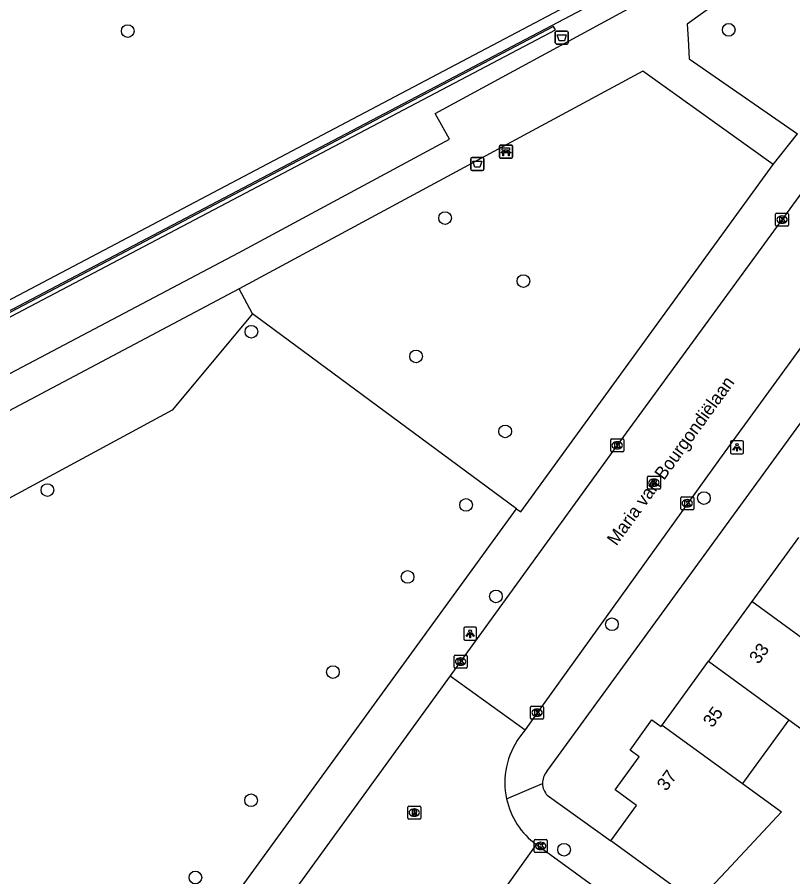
# Model space of a CAD drawing. Extents: x 159675 to 160530, y 382179 to 382901.
# Drawn here: x 160100.6 to 160160.3, y 382626.9 to 382693.1 of the extents above; entities that cross this region are included whole.
import ezdxf

# ---------------------------------------------------------------- set-up
doc = ezdxf.new("R2010")
doc.units = 0
for name, color, linetype in [('IMGEO_Afvalbak', 7, 'Continuous'), ('IMGEO_Bank', 7, 'Continuous'), ('IMGEO_Boom', 7, 'Continuous'), ('IMGEO_Groenvoorziening', 7, 'Continuous'), ('IMGEO_Haag', 7, 'Continuous'), ('IMGEO_Hek', 7, 'Continuous'), ('IMGEO_Kolk', 7, 'Continuous'), ('IMGEO_Lichtpunt', 7, 'Continuous'), ('IMGEO_Openbare_ruimte_label', 7, 'Continuous'), ('IMGEO_Pand', 7, 'Continuous'), ('IMGEO_Pand_nummerreeks', 7, 'Continuous'), ('IMGEO_Rijbaan_lokaal_open', 7, 'Continuous'), ('IMGEO_Rioolput', 7, 'Continuous'), ('IMGEO_Voetpad_halfverhard', 7, 'Continuous'), ('IMGEO_Voetpad_open', 7, 'Continuous')]:
    doc.layers.add(name, color=color, linetype=linetype)

msp = doc.modelspace()

# ---------------------------------------------------------------- linework, layer by layer
at = {"layer": 'IMGEO_Afvalbak'}
for p, q in [((160142.023, 382691.123), (160142.023, 382691.923)), ((160142.023, 382691.923), (160142.023, 382691.123)), ((160142.123, 382692.023), (160142.913, 382692.023)), ((160142.913, 382692.023), (160142.123, 382692.023)), ((160143.013, 382691.923), (160143.013, 382691.123)), ((160143.013, 382691.123), (160143.013, 382691.923)), ((160142.913, 382691.023), (160142.123, 382691.023)), ((160142.123, 382691.023), (160142.913, 382691.023)), ((160135.62, 382682.278), (160136.41, 382682.278)), ((160136.41, 382682.278), (160135.62, 382682.278)), ((160135.52, 382681.378), (160135.52, 382682.178)), ((160135.52, 382682.178), (160135.52, 382681.378)), ((160136.51, 382682.178), (160136.51, 382681.378)), ((160136.51, 382681.378), (160136.51, 382682.178)), ((160136.41, 382681.278), (160135.62, 382681.278)), ((160135.62, 382681.278), (160136.41, 382681.278))]:
    msp.add_line(p, q, dxfattribs=at)
for points in [[(160142.166, 382691.737), (160142.87, 382691.737), (160142.721, 382691.267), (160142.315, 382691.267), (160142.166, 382691.737)], [(160135.663, 382681.992), (160136.367, 382681.992), (160136.218, 382681.522), (160135.812, 382681.522), (160135.663, 382681.992)]]:
    msp.add_lwpolyline(points, dxfattribs=at)
for centre, start, end in [((160142.123, 382691.923), 90, 180), ((160142.123, 382691.923), 90, 180), ((160142.913, 382691.923), 0, 90), ((160142.913, 382691.923), 360, 90), ((160142.123, 382691.123), 180, 270), ((160142.123, 382691.123), 180, 270), ((160142.913, 382691.123), 270, 0), ((160142.913, 382691.123), 270, 0), ((160135.62, 382682.178), 90, 180), ((160135.62, 382682.178), 90, 180), ((160136.41, 382682.178), 0, 90), ((160136.41, 382682.178), 360, 90), ((160135.62, 382681.378), 180, 270), ((160135.62, 382681.378), 180, 270), ((160136.41, 382681.378), 270, 0), ((160136.41, 382681.378), 270, 0)]:
    msp.add_arc(centre, 0.1, start, end, dxfattribs=at)
at = {"layer": 'IMGEO_Bank'}
for p, q in [((160137.722, 382682.311), (160137.722, 382683.152)), ((160137.722, 382683.152), (160137.722, 382682.311)), ((160137.797, 382683.236), (160138.638, 382683.236)), ((160138.638, 382683.236), (160137.797, 382683.236)), ((160138.722, 382683.161), (160138.722, 382682.32)), ((160138.722, 382682.32), (160138.722, 382683.161)), ((160138.419, 382682.634), (160138.026, 382682.634)), ((160138.031, 382682.742), (160138.031, 382682.848)), ((160138.075, 382682.848), (160138.075, 382682.742)), ((160138.363, 382682.854), (160138.081, 382682.854)), ((160138.081, 382682.736), (160138.363, 382682.736)), ((160138.369, 382682.742), (160138.369, 382682.848)), ((160138.413, 382682.848), (160138.413, 382682.742)), ((160138.647, 382682.236), (160137.806, 382682.236)), ((160137.806, 382682.236), (160138.647, 382682.236))]:
    msp.add_line(p, q, dxfattribs=at)
for points in [[(160138.025, 382682.854), (160137.939, 382682.854), (160137.939, 382683.015), (160138.502, 382683.015), (160138.502, 382682.854), (160138.419, 382682.854)], [(160137.969, 382682.634), (160137.827, 382682.634), (160137.939, 382682.736), (160138.025, 382682.736)], [(160138.019, 382682.627), (160138.019, 382682.42), (160137.976, 382682.42), (160137.976, 382682.627)], [(160138.419, 382682.736), (160138.502, 382682.736), (160138.614, 382682.634), (160138.475, 382682.634)], [(160138.469, 382682.627), (160138.469, 382682.42), (160138.425, 382682.42), (160138.425, 382682.627)]]:
    msp.add_lwpolyline(points, dxfattribs=at)
for centre, radius, start, end in [((160137.8, 382683.158), 0.0779, 92.4484, 184.28452), ((160137.8, 382683.158), 0.0779, 92.4484, 184.28452), ((160138.644, 382683.158), 0.0779, 2.4484, 94.28452), ((160138.644, 382683.158), 0.0779, 2.4484, 94.28452), ((160137.8, 382682.314), 0.0779, 182.4484, 274.28452), ((160137.8, 382682.314), 0.0779, 182.4484, 274.28452), ((160137.969, 382682.627), 0.00671, 2.89567, 87.10433), ((160138.026, 382682.627), 0.00671, 92.89567, 177.10433), ((160138.024, 382682.847), 0.00671, 2.89567, 87.10433), ((160138.024, 382682.743), 0.00671, 272.89567, 357.10433), ((160138.081, 382682.847), 0.00671, 92.89567, 177.10433), ((160138.081, 382682.743), 0.00671, 182.89567, 267.10433), ((160138.363, 382682.847), 0.00671, 2.89567, 87.10433), ((160138.363, 382682.743), 0.00671, 272.89567, 357.10433), ((160138.42, 382682.847), 0.00671, 92.89567, 177.10433), ((160138.42, 382682.743), 0.00671, 182.89567, 267.10433), ((160138.418, 382682.627), 0.00671, 2.89567, 87.10433), ((160138.475, 382682.627), 0.00671, 92.89567, 177.10433), ((160138.644, 382682.314), 0.0779, 272.4484, 4.28452), ((160138.644, 382682.314), 0.0779, 272.4484, 4.28452)]:
    msp.add_arc(centre, radius, start, end, dxfattribs=at)
at = {"layer": 'IMGEO_Boom'}
for centre in [(160109.074, 382692.021), (160155.384, 382692.115), (160133.528, 382677.612), (160139.568, 382672.758), (160118.608, 382668.855), (160131.298, 382666.954), (160138.16, 382661.171), (160102.892, 382656.654), (160153.471, 382656.038), (160135.153, 382655.509), (160130.636, 382649.963), (160137.452, 382648.464), (160146.382, 382646.319), (160124.888, 382642.636), (160118.576, 382632.758), (160142.699, 382628.945), (160114.289, 382626.806)]:
    msp.add_circle(centre, 0.489, dxfattribs=at)
at = {"layer": 'IMGEO_Groenvoorziening'}
for points in [[(160028.302, 382652.839), (160035.617, 382637.39), (160147.024, 382696.155), (160135.659, 382717.176)], [(160118.682, 382670.24), (160117.651, 382672.153)], [(160118.682, 382670.24), (160112.498, 382662.82), (160085.741, 382648.366), (160074.078, 382641.993)], [(160139.025, 382655.211), (160118.682, 382670.24)]]:
    msp.add_lwpolyline(points, dxfattribs=at)
at = {"layer": 'IMGEO_Haag'}
msp.add_lwpolyline([(160142.038, 382692.112), (160141.896, 382692.376), (160088.197, 382664.142), (160088.386, 382663.89), (160142.038, 382692.112)], dxfattribs=at)
at = {"layer": 'IMGEO_Hek'}
msp.add_lwpolyline([(160023.484, 382662.997), (160024.119, 382661.659), (160025.128, 382659.531), (160027.238, 382655.082), (160028.302, 382652.839), (160035.908, 382636.803), (160148.158, 382695.844), (160136.928, 382717.961), (160135.789, 382720.203), (160134.215, 382723.303), (160133.5, 382724.713), (160132.248, 382727.178), (160131.343, 382728.961)], dxfattribs=at)
at = {"layer": 'IMGEO_Kolk'}
for p, q in [((160159, 382677.068), (160159, 382677.92)), ((160159.075, 382677.994), (160159.927, 382677.994)), ((160159.488, 382677.774), (160159.513, 382677.774)), ((160160.001, 382677.92), (160160.001, 382677.068)), ((160159.927, 382676.994), (160159.075, 382676.994)), ((160159.511, 382677.214), (160159.486, 382677.214)), ((160146.291, 382659.678), (160146.291, 382660.53)), ((160146.366, 382660.604), (160147.218, 382660.604)), ((160146.779, 382660.384), (160146.804, 382660.384)), ((160147.292, 382660.53), (160147.292, 382659.678)), ((160146.802, 382659.824), (160146.777, 382659.824)), ((160147.218, 382659.604), (160146.366, 382659.604)), ((160151.686, 382655.213), (160151.686, 382656.065)), ((160151.761, 382656.139), (160152.613, 382656.139)), ((160152.174, 382655.919), (160152.199, 382655.919)), ((160152.687, 382656.065), (160152.687, 382655.213)), ((160152.613, 382655.139), (160151.761, 382655.139)), ((160152.197, 382655.359), (160152.172, 382655.359)), ((160134.222, 382643.019), (160134.222, 382643.871)), ((160134.297, 382643.945), (160135.149, 382643.945)), ((160135.223, 382643.871), (160135.223, 382643.019)), ((160134.733, 382643.165), (160134.708, 382643.165)), ((160134.71, 382643.725), (160134.735, 382643.725)), ((160135.149, 382642.945), (160134.297, 382642.945)), ((160140.119, 382639.079), (160140.119, 382639.931)), ((160140.194, 382640.005), (160141.046, 382640.005)), ((160141.12, 382639.931), (160141.12, 382639.079)), ((160140.63, 382639.225), (160140.605, 382639.225)), ((160140.607, 382639.785), (160140.632, 382639.785)), ((160141.046, 382639.005), (160140.194, 382639.005)), ((160140.4, 382628.811), (160140.4, 382629.663)), ((160140.475, 382629.737), (160141.327, 382629.737)), ((160140.888, 382629.517), (160140.913, 382629.517)), ((160141.401, 382629.663), (160141.401, 382628.811)), ((160141.327, 382628.737), (160140.475, 382628.737)), ((160140.911, 382628.957), (160140.886, 382628.957))]:
    msp.add_line(p, q, dxfattribs=at)
for points in [[(160159, 382677.068), (160159, 382677.92)], [(160159.075, 382677.994), (160159.927, 382677.994)], [(160159.321, 382677.694), (160159.444, 382677.694), (160159.444, 382677.543), (160159.574, 382677.694), (160159.738, 382677.694), (160159.592, 382677.543), (160159.745, 382677.294), (160159.593, 382677.294), (160159.508, 382677.458), (160159.444, 382677.391), (160159.444, 382677.294), (160159.321, 382677.294), (160159.321, 382677.694)], [(160160.001, 382677.92), (160160.001, 382677.068)], [(160159.927, 382676.994), (160159.075, 382676.994)], [(160146.291, 382659.678), (160146.291, 382660.53)], [(160146.366, 382660.604), (160147.218, 382660.604)], [(160147.292, 382660.53), (160147.292, 382659.678)], [(160146.612, 382660.304), (160146.735, 382660.304), (160146.735, 382660.153), (160146.865, 382660.304), (160147.029, 382660.304), (160146.883, 382660.153), (160147.036, 382659.904), (160146.884, 382659.904), (160146.799, 382660.068), (160146.735, 382660.001), (160146.735, 382659.904), (160146.612, 382659.904), (160146.612, 382660.304)], [(160147.218, 382659.604), (160146.366, 382659.604)], [(160151.686, 382655.213), (160151.686, 382656.065)], [(160151.761, 382656.139), (160152.613, 382656.139)], [(160152.007, 382655.839), (160152.13, 382655.839), (160152.13, 382655.688), (160152.26, 382655.839), (160152.424, 382655.839), (160152.278, 382655.688), (160152.431, 382655.439), (160152.279, 382655.439), (160152.194, 382655.603), (160152.13, 382655.536), (160152.13, 382655.439), (160152.007, 382655.439), (160152.007, 382655.839)], [(160152.687, 382656.065), (160152.687, 382655.213)], [(160152.613, 382655.139), (160151.761, 382655.139)], [(160134.222, 382643.019), (160134.222, 382643.871)], [(160134.297, 382643.945), (160135.149, 382643.945)], [(160135.223, 382643.871), (160135.223, 382643.019)], [(160134.543, 382643.645), (160134.666, 382643.645), (160134.666, 382643.494), (160134.796, 382643.645), (160134.96, 382643.645), (160134.814, 382643.494), (160134.967, 382643.245), (160134.815, 382643.245), (160134.73, 382643.409), (160134.666, 382643.342), (160134.666, 382643.245), (160134.543, 382643.245), (160134.543, 382643.645)], [(160135.149, 382642.945), (160134.297, 382642.945)], [(160140.119, 382639.079), (160140.119, 382639.931)], [(160140.194, 382640.005), (160141.046, 382640.005)], [(160141.12, 382639.931), (160141.12, 382639.079)], [(160140.44, 382639.705), (160140.563, 382639.705), (160140.563, 382639.554), (160140.693, 382639.705), (160140.857, 382639.705), (160140.711, 382639.554), (160140.864, 382639.305), (160140.712, 382639.305), (160140.627, 382639.469), (160140.563, 382639.402), (160140.563, 382639.305), (160140.44, 382639.305), (160140.44, 382639.705)], [(160141.046, 382639.005), (160140.194, 382639.005)], [(160140.4, 382628.811), (160140.4, 382629.663)], [(160140.475, 382629.737), (160141.327, 382629.737)], [(160140.721, 382629.437), (160140.844, 382629.437), (160140.844, 382629.286), (160140.974, 382629.437), (160141.138, 382629.437), (160140.992, 382629.286), (160141.145, 382629.037), (160140.993, 382629.037), (160140.908, 382629.201), (160140.844, 382629.134), (160140.844, 382629.037), (160140.721, 382629.037), (160140.721, 382629.437)], [(160141.401, 382629.663), (160141.401, 382628.811)], [(160141.327, 382628.737), (160140.475, 382628.737)]]:
    msp.add_lwpolyline(points, dxfattribs=at)
for centre, start, end in [((160159.077, 382677.918), 91.55205, 178.44795), ((160159.077, 382677.918), 91.55205, 178.44795), ((160159.925, 382677.918), 1.55205, 88.44795), ((160159.925, 382677.918), 1.55205, 88.44795), ((160159.077, 382677.07), 181.55205, 268.44795), ((160159.077, 382677.07), 181.55205, 268.44795), ((160159.925, 382677.07), 271.55205, 358.44795), ((160159.925, 382677.07), 271.55205, 358.44795), ((160146.368, 382660.528), 91.55205, 178.44795), ((160146.368, 382660.528), 91.55205, 178.44795), ((160147.216, 382660.528), 1.55205, 88.44795), ((160147.216, 382660.528), 1.55205, 88.44795), ((160146.368, 382659.68), 181.55205, 268.44795), ((160146.368, 382659.68), 181.55205, 268.44795), ((160147.216, 382659.68), 271.55205, 358.44795), ((160147.216, 382659.68), 271.55205, 358.44795), ((160151.763, 382656.063), 91.55205, 178.44795), ((160151.763, 382656.063), 91.55205, 178.44795), ((160152.611, 382656.063), 1.55205, 88.44795), ((160152.611, 382656.063), 1.55205, 88.44795), ((160151.763, 382655.215), 181.55205, 268.44795), ((160151.763, 382655.215), 181.55205, 268.44795), ((160152.611, 382655.215), 271.55205, 358.44795), ((160152.611, 382655.215), 271.55205, 358.44795), ((160134.299, 382643.869), 91.55205, 178.44795), ((160134.299, 382643.869), 91.55205, 178.44795), ((160135.147, 382643.869), 1.55205, 88.44795), ((160135.147, 382643.869), 1.55205, 88.44795), ((160134.299, 382643.021), 181.55205, 268.44795), ((160134.299, 382643.021), 181.55205, 268.44795), ((160135.147, 382643.021), 271.55205, 358.44795), ((160135.147, 382643.021), 271.55205, 358.44795), ((160140.196, 382639.929), 91.55205, 178.44795), ((160140.196, 382639.929), 91.55205, 178.44795), ((160141.044, 382639.929), 1.55205, 88.44795), ((160141.044, 382639.929), 1.55205, 88.44795), ((160140.196, 382639.081), 181.55205, 268.44795), ((160140.196, 382639.081), 181.55205, 268.44795), ((160141.044, 382639.081), 271.55205, 358.44795), ((160141.044, 382639.081), 271.55205, 358.44795), ((160140.477, 382629.661), 91.55205, 178.44795), ((160140.477, 382629.661), 91.55205, 178.44795), ((160141.325, 382629.661), 1.55205, 88.44795), ((160141.325, 382629.661), 1.55205, 88.44795), ((160140.477, 382628.813), 181.55205, 268.44795), ((160140.477, 382628.813), 181.55205, 268.44795), ((160141.325, 382628.813), 271.55205, 358.44795), ((160141.325, 382628.813), 271.55205, 358.44795)]:
    msp.add_arc(centre, 0.0765, start, end, dxfattribs=at)
for centre, major_axis, ratio, start_param, end_param in [((160159.487, 382677.494), (-0.387, 0.002), 0.722429, 4.712389, 7.853982), ((160159.512, 382677.494), (-0.39, 0.002), 0.717154, 1.570796, 4.712389), ((160146.778, 382660.104), (-0.387, 0.002), 0.722429, 4.712389, 7.853982), ((160146.803, 382660.104), (-0.39, 0.002), 0.717154, 1.570796, 4.712389), ((160152.173, 382655.639), (-0.387, 0.002), 0.722429, 4.712389, 7.853982), ((160152.198, 382655.639), (-0.39, 0.002), 0.717154, 1.570796, 4.712389), ((160134.709, 382643.445), (-0.387, 0.002), 0.722429, 4.712389, 7.853982), ((160134.734, 382643.445), (-0.39, 0.002), 0.717154, 1.570796, 4.712389), ((160140.606, 382639.505), (-0.387, 0.002), 0.722429, 4.712389, 7.853982), ((160140.631, 382639.505), (-0.39, 0.002), 0.717154, 1.570796, 4.712389), ((160140.887, 382629.237), (-0.387, 0.002), 0.722429, 4.712389, 7.853982), ((160140.912, 382629.237), (-0.39, 0.002), 0.717154, 1.570796, 4.712389)]:
    msp.add_ellipse(centre, major_axis=major_axis, ratio=ratio, start_param=start_param, end_param=end_param, dxfattribs=at)
at = {"layer": 'IMGEO_Lichtpunt'}
for p, q in [((160156.428, 382660.452), (160155.62, 382660.452)), ((160156.428, 382660.452), (160155.62, 382660.452)), ((160155.526, 382660.357), (160155.526, 382659.55)), ((160155.526, 382660.357), (160155.526, 382659.55)), ((160156.522, 382659.55), (160156.522, 382660.357)), ((160156.522, 382659.55), (160156.522, 382660.357)), ((160155.62, 382659.456), (160156.428, 382659.456)), ((160155.62, 382659.456), (160156.428, 382659.456)), ((160134.966, 382645.99), (160134.966, 382645.183)), ((160134.966, 382645.99), (160134.966, 382645.183)), ((160135.868, 382646.085), (160135.06, 382646.085)), ((160135.868, 382646.085), (160135.06, 382646.085)), ((160135.962, 382645.183), (160135.962, 382645.99)), ((160135.962, 382645.183), (160135.962, 382645.99)), ((160135.06, 382645.089), (160135.868, 382645.089)), ((160135.06, 382645.089), (160135.868, 382645.089))]:
    msp.add_line(p, q, dxfattribs=at)
for points in [[(160155.9, 382660.021), (160155.939, 382659.993), (160155.751, 382659.731), (160155.713, 382659.758), (160155.9, 382660.021)], [(160156.002, 382659.973), (160156.049, 382659.973), (160156.049, 382659.651), (160156.002, 382659.651), (160156.002, 382659.973)], [(160156.112, 382659.993), (160156.15, 382660.02), (160156.337, 382659.758), (160156.298, 382659.73), (160156.112, 382659.993)], [(160135.34, 382645.654), (160135.379, 382645.626), (160135.191, 382645.364), (160135.153, 382645.391), (160135.34, 382645.654)], [(160135.442, 382645.606), (160135.489, 382645.606), (160135.489, 382645.284), (160135.442, 382645.284), (160135.442, 382645.606)], [(160135.552, 382645.626), (160135.59, 382645.653), (160135.777, 382645.391), (160135.738, 382645.363), (160135.552, 382645.626)]]:
    msp.add_lwpolyline(points, dxfattribs=at)
for centre in [(160156.025, 382660.155), (160135.465, 382645.788)]:
    msp.add_circle(centre, 0.0994, dxfattribs=at)
for centre, start, end in [((160155.62, 382660.357), 90, 180), ((160155.62, 382660.357), 90, 180), ((160156.428, 382660.357), 0, 90), ((160156.428, 382660.357), 0, 90), ((160155.62, 382659.55), 180, 270), ((160155.62, 382659.55), 180, 270), ((160156.428, 382659.55), 270, 0), ((160156.428, 382659.55), 270, 360), ((160135.06, 382645.99), 90, 180), ((160135.06, 382645.99), 90, 180), ((160135.868, 382645.99), 0, 90), ((160135.868, 382645.99), 0, 90), ((160135.06, 382645.183), 180, 270), ((160135.06, 382645.183), 180, 270), ((160135.868, 382645.183), 270, 0), ((160135.868, 382645.183), 270, 360)]:
    msp.add_arc(centre, 0.0946, start, end, dxfattribs=at)
at = {"layer": 'IMGEO_Pand'}
for points in [[(160160.763, 382653.001), (160157.172, 382648.061)], [(160157.172, 382648.061), (160153.83, 382643.463)], [(160165.928, 382641.699), (160163.365, 382643.561), (160157.172, 382648.061)], [(160150.249, 382638.537), (160153.83, 382643.463)], [(160153.83, 382643.463), (160160.022, 382638.963)], [(160160.022, 382638.963), (160163.461, 382636.464), (160166.803, 382641.063), (160165.928, 382641.699)], [(160146.308, 382629.63), (160148.288, 382632.355), (160146.63, 382633.559), (160148.483, 382636.107), (160147.78, 382636.619), (160149.467, 382638.941), (160150.17, 382638.429), (160150.249, 382638.537)], [(160150.249, 382638.537), (160156.441, 382634.037)], [(160160.022, 382638.963), (160156.441, 382634.037)], [(160156.441, 382634.037), (160159.44, 382631.857), (160155.204, 382627.327), (160152.983, 382624.952)], [(160152.983, 382624.952), (160152.887, 382624.85), (160146.308, 382629.63)]]:
    msp.add_lwpolyline(points, dxfattribs=at)
at = {"layer": 'IMGEO_Rijbaan_lokaal_open'}
for points in [[(160161.775, 382680.602), (160146.792, 382660.104), (160134.723, 382643.445), (160133.916, 382642.352)], [(160165.176, 382673.46), (160154.667, 382659.043), (160140.62, 382639.505), (160139.698, 382638.176)], [(160133.916, 382642.352), (160121.569, 382625.329)], [(160133.916, 382642.352), (160139.698, 382638.176)], [(160139.698, 382638.176), (160139.276, 382637.61)], [(160140.555, 382629.351), (160136.439, 382623.587)], [(160245.716, 382552.786), (160140.763, 382629.192), (160140.555, 382629.351)]]:
    msp.add_lwpolyline(points, dxfattribs=at)
for centre, radius, start, end in [((160144.047, 382634.121), 5.911, 143.82181, 192.3036), ((160144.044, 382634.118), 5.907, 192.2824, 233.79975)]:
    msp.add_arc(centre, radius, start, end, dxfattribs=at)
at = {"layer": 'IMGEO_Rioolput'}
for p, q in [((160149.116, 382656.8), (160149.116, 382657.652)), ((160149.191, 382657.726), (160150.043, 382657.726)), ((160149.604, 382657.506), (160149.629, 382657.506)), ((160150.117, 382657.652), (160150.117, 382656.8)), ((160150.043, 382656.726), (160149.191, 382656.726)), ((160149.627, 382656.946), (160149.602, 382656.946)), ((160130.656, 382631.38), (160130.656, 382632.232)), ((160130.731, 382632.306), (160131.583, 382632.306)), ((160131.144, 382632.086), (160131.169, 382632.086)), ((160131.657, 382632.232), (160131.657, 382631.38)), ((160131.583, 382631.306), (160130.731, 382631.306)), ((160131.167, 382631.526), (160131.142, 382631.526))]:
    msp.add_line(p, q, dxfattribs=at)
for points in [[(160149.116, 382656.8), (160149.116, 382657.652)], [(160149.191, 382657.726), (160150.043, 382657.726)], [(160149.705, 382657.424), (160149.453, 382657.426), (160149.453, 382657.026)], [(160149.453, 382657.026), (160149.577, 382657.026), (160149.577, 382657.188), (160149.588, 382657.188)], [(160149.631, 382657.345), (160149.577, 382657.345), (160149.577, 382657.264)], [(160149.577, 382657.264), (160149.629, 382657.264)], [(160149.635, 382657.159), (160149.706, 382657.026), (160149.846, 382657.026), (160149.781, 382657.152)], [(160150.117, 382657.652), (160150.117, 382656.8)], [(160150.043, 382656.726), (160149.191, 382656.726)], [(160130.656, 382631.38), (160130.656, 382632.232)], [(160130.731, 382632.306), (160131.583, 382632.306)], [(160131.245, 382632.004), (160130.993, 382632.006), (160130.993, 382631.606)], [(160131.171, 382631.925), (160131.117, 382631.925), (160131.117, 382631.844)], [(160131.657, 382632.232), (160131.657, 382631.38)], [(160131.583, 382631.306), (160130.731, 382631.306)], [(160130.993, 382631.606), (160131.117, 382631.606), (160131.117, 382631.768), (160131.128, 382631.768)], [(160131.117, 382631.844), (160131.169, 382631.844)], [(160131.175, 382631.739), (160131.246, 382631.606), (160131.386, 382631.606), (160131.321, 382631.732)]]:
    msp.add_lwpolyline(points, dxfattribs=at)
for centre, radius, start, end in [((160149.193, 382657.65), 0.0765, 91.55205, 178.44795), ((160149.193, 382657.65), 0.0765, 91.55205, 178.44795), ((160149.587, 382657.135), 0.0533, 26.02933, 88.69889), ((160149.613, 382657.453), 0.19, 274.7715, 282.96867), ((160149.637, 382657.249), 0.0964, 77.00612, 93.18647), ((160149.651, 382657.306), 0.0378, 276.66336, 79.67722), ((160149.704, 382657.314), 0.109, 350.36119, 89.41601), ((160149.702, 382657.314), 0.112, 277.58423, 350.98172), ((160149.686, 382657.099), 0.108, 29.51342, 73.79051), ((160150.041, 382657.65), 0.0765, 1.55205, 88.44795), ((160150.041, 382657.65), 0.0765, 1.55205, 88.44795), ((160149.193, 382656.802), 0.0765, 181.55205, 268.44795), ((160149.193, 382656.802), 0.0765, 181.55205, 268.44795), ((160150.041, 382656.802), 0.0765, 271.55205, 358.44795), ((160150.041, 382656.802), 0.0765, 271.55205, 358.44795), ((160130.733, 382632.23), 0.0765, 91.55205, 178.44795), ((160130.733, 382632.23), 0.0765, 91.55205, 178.44795), ((160131.177, 382631.829), 0.0964, 77.00612, 93.18647), ((160131.191, 382631.886), 0.0378, 276.66336, 79.67722), ((160131.244, 382631.894), 0.109, 350.36119, 89.41601), ((160131.581, 382632.23), 0.0765, 1.55205, 88.44795), ((160131.581, 382632.23), 0.0765, 1.55205, 88.44795), ((160130.733, 382631.382), 0.0765, 181.55205, 268.44795), ((160130.733, 382631.382), 0.0765, 181.55205, 268.44795), ((160131.127, 382631.715), 0.0533, 26.02933, 88.69889), ((160131.153, 382632.033), 0.19, 274.7715, 282.96867), ((160131.242, 382631.894), 0.112, 277.58423, 350.98172), ((160131.226, 382631.679), 0.108, 29.51342, 73.79051), ((160131.581, 382631.382), 0.0765, 271.55205, 358.44795), ((160131.581, 382631.382), 0.0765, 271.55205, 358.44795)]:
    msp.add_arc(centre, radius, start, end, dxfattribs=at)
for centre, major_axis, ratio, start_param, end_param in [((160149.603, 382657.226), (-0.387, 0.002), 0.722429, 4.712389, 7.853982), ((160149.628, 382657.226), (-0.39, 0.002), 0.717154, 1.570796, 4.712389), ((160131.143, 382631.806), (-0.387, 0.002), 0.722429, 4.712389, 7.853982), ((160131.168, 382631.806), (-0.39, 0.002), 0.717154, 1.570796, 4.712389)]:
    msp.add_ellipse(centre, major_axis=major_axis, ratio=ratio, start_param=start_param, end_param=end_param, dxfattribs=at)
at = {"layer": 'IMGEO_Voetpad_halfverhard'}
for points in [[(160195.172, 382715.185), (160176.655, 382705.893), (160155.741, 382695.129), (160152.195, 382692.551), (160152.254, 382691.404), (160152.332, 382689.883), (160160.682, 382684.114)], [(160026.864, 382627.053), (160039.438, 382633.696), (160117.599, 382674.927), (160133.867, 382683.693), (160132.766, 382685.663), (160147.637, 382693.732), (160185.379, 382713.701)], [(160158.819, 382681.732), (160148.758, 382688.93), (160117.651, 382672.153)], [(160117.651, 382672.153), (160116.793, 382671.69), (160071.154, 382647.509)]]:
    msp.add_lwpolyline(points, dxfattribs=at)
at = {"layer": 'IMGEO_Voetpad_open'}
for points in [[(160158.819, 382681.732), (160160.682, 382684.114)], [(160139.025, 382655.211), (160139.364, 382654.969), (160158.819, 382681.732)], [(160141.366, 382634.961), (160167.947, 382671.456)], [(160073.24, 382564.766), (160078.977, 382572.654), (160139.025, 382655.211)], [(160138.272, 382632.861), (160141.04, 382634.043)], [(160141.407, 382633.141), (160146.308, 382629.63)]]:
    msp.add_lwpolyline(points, dxfattribs=at)
for centre, radius, start, end in [((160142.414, 382634.072), 1.375, 139.69461, 181.20347), ((160142.413, 382634.076), 1.373, 181.3703, 222.90992)]:
    msp.add_arc(centre, radius, start, end, dxfattribs=at)

# ---------------------------------------------------------------- texts
at = {"layer": 'IMGEO_Openbare_ruimte_label'}
msp.add_text('Maria van Bourgondiëlaan', height=1, rotation=54.11589, dxfattribs=at).set_placement((160146.733, 382652.305))
at = {"layer": 'IMGEO_Pand_nummerreeks'}
for s, rotation, p in [('33', 53.98408, (160157.684, 382643.188)), ('35', 53.98577, (160154.13, 382638.297)), ('37', 53.98408, (160150.574, 382633.407))]:
    msp.add_text(s, height=1, rotation=rotation, dxfattribs=at).set_placement(p)

doc.saveas('drawing.dxf')
